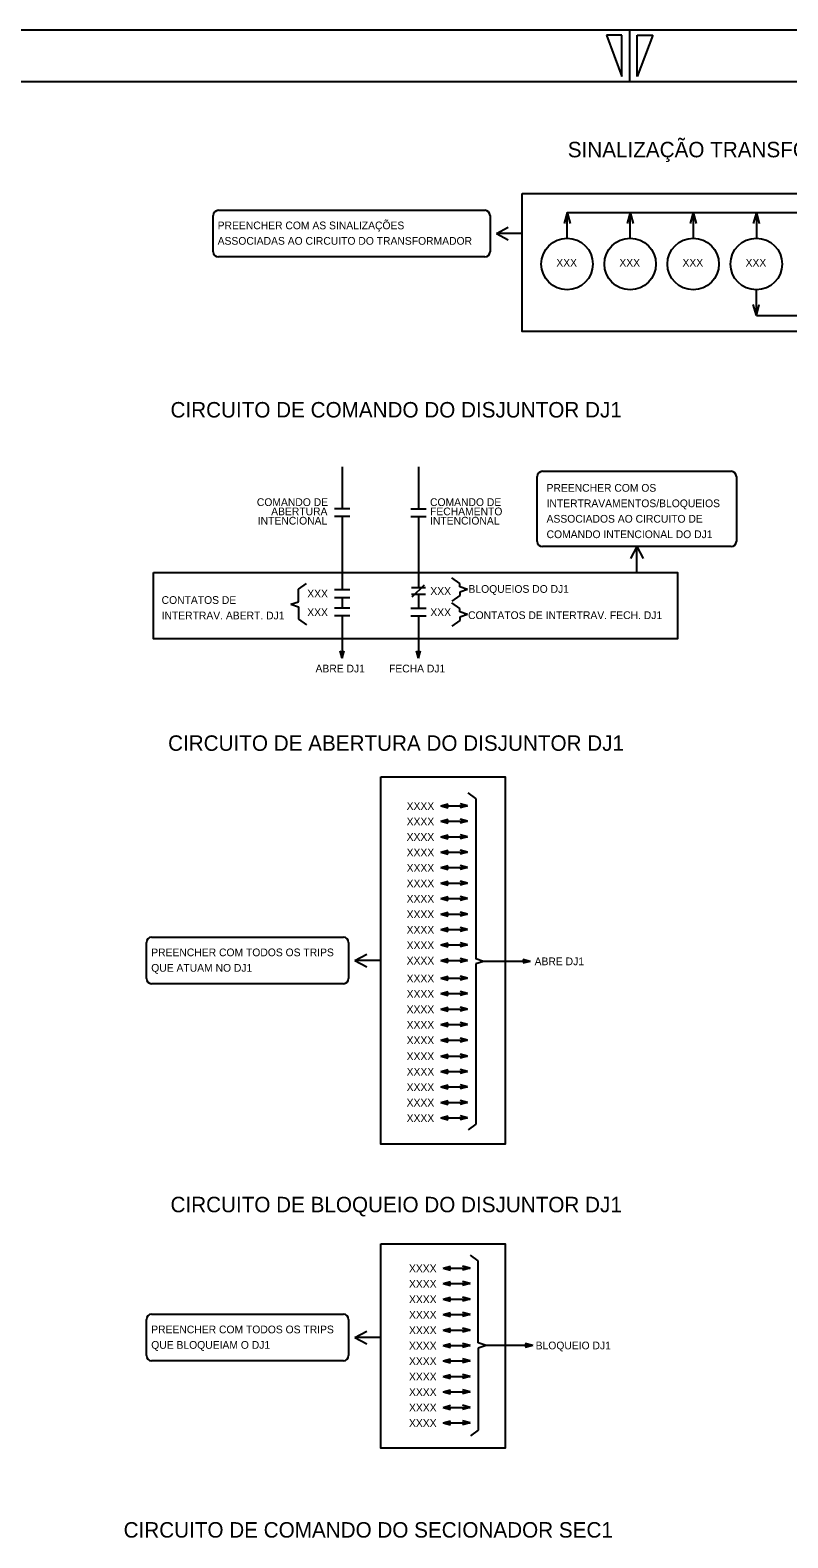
# Model space of a CAD drawing. Extents: x 563 to 1404, y 358 to 952.
# Drawn here: x 1102.2 to 1249.3, y 659.5 to 952 of the extents above; entities that cross this region are included whole.
import ezdxf

# ---------------------------------------------------------------- set-up
doc = ezdxf.new("R2010")
doc.units = 0
doc.layers.add('New Level (0)', color=7, linetype='Continuous')

# ---------------------------------------------------------------- blocks, each defined once
blk = doc.blocks.new('39')
for p, q in [((0, 0), (1.45, 0.39)), ((0, 0), (5.22, 0)), ((0, 0), (1.45, -0.39)), ((5.22, 0), (3.77, 0.39)), ((5.22, 0), (3.77, -0.39))]:
    blk.add_line(p, q)

msp = doc.modelspace()

# ---------------------------------------------------------------- linework, layer by layer
for p, q in [((1206.46, 916.59), (1205.87, 914.42)), ((1206.46, 911.59), (1206.46, 916.59)), ((1206.46, 916.59), (1265.58, 916.59)), ((1206.46, 916.59), (1207.04, 914.42)), ((1218.7, 916.59), (1218.12, 914.42)), ((1218.7, 911.59), (1218.7, 916.59)), ((1218.7, 916.59), (1219.28, 914.42)), ((1230.94, 916.59), (1230.36, 914.42)), ((1230.94, 916.59), (1230.94, 911.59)), ((1230.94, 916.59), (1231.53, 914.42)), ((1243.19, 916.59), (1242.6, 914.42)), ((1243.19, 916.59), (1243.19, 911.59)), ((1243.19, 916.59), (1243.77, 914.42)), ((1243.19, 896.59), (1243.19, 901.59)), ((1243.19, 896.59), (1242.6, 898.77)), ((1243.19, 896.59), (1243.77, 898.77)), ((1243.19, 896.59), (1265.58, 896.59)), ((1162.82, 867.28), (1162.82, 859.1)), ((1177.61, 867.28), (1177.61, 859.1)), ((1164.32, 859.1), (1161.32, 859.1)), ((1164.32, 857.6), (1161.32, 857.6)), ((1162.82, 857.6), (1162.82, 843.36)), ((1176.11, 859.1), (1179.11, 859.1)), ((1176.11, 857.6), (1179.11, 857.6)), ((1177.61, 857.6), (1177.61, 843.86)), ((1185.62, 844.64), (1184.12, 845.72)), ((1154.36, 843.55), (1155.86, 844.63)), ((1154.36, 841.08), (1154.36, 843.55)), ((1164.32, 843.36), (1161.32, 843.36)), ((1176.26, 843.86), (1178.96, 843.86)), ((1178.96, 842.51), (1176.26, 842.51)), ((1176.42, 842), (1178.8, 844.38)), ((1177.61, 842.36), (1177.61, 839.86)), ((1185.62, 843.96), (1185.62, 844.64)), ((1187.12, 843.46), (1185.62, 843.96)), ((1187.12, 843.46), (1185.62, 842.96)), ((1185.62, 842.96), (1185.62, 842.27)), ((1152.86, 840.58), (1154.36, 841.08)), ((1152.86, 840.58), (1154.36, 840.08)), ((1154.36, 840.08), (1154.36, 837.68)), ((1164.32, 841.86), (1161.32, 841.86)), ((1164.32, 839.86), (1161.32, 839.86)), ((1162.82, 841.86), (1162.82, 839.86)), ((1176.11, 839.86), (1179.11, 839.86)), ((1176.11, 839.86), (1179.11, 839.86)), ((1185.62, 842.27), (1184.12, 841.19)), ((1185.62, 839.78), (1184.12, 840.87)), ((1185.62, 839.1), (1185.62, 839.78)), ((1154.36, 837.68), (1155.86, 836.6)), ((1164.32, 838.36), (1161.32, 838.36)), ((1162.82, 838.36), (1162.82, 830.12)), ((1176.11, 838.36), (1179.11, 838.36)), ((1176.11, 838.36), (1179.11, 838.36)), ((1177.61, 838.36), (1177.61, 830.12)), ((1185.62, 837.42), (1184.12, 836.33)), ((1187.12, 838.6), (1185.62, 839.1)), ((1187.12, 838.6), (1185.62, 838.1)), ((1185.62, 838.1), (1185.62, 837.42)), ((1162.82, 830.12), (1162.43, 831.57)), ((1162.82, 830.12), (1163.21, 831.57)), ((1177.61, 830.12), (1177.22, 831.57)), ((1177.61, 830.12), (1178, 831.57)), ((1181.94, 801.5), (1183.39, 801.89)), ((1181.94, 801.5), (1187.16, 801.5)), ((1181.94, 801.5), (1183.39, 801.11)), ((1187.16, 801.5), (1185.71, 801.89)), ((1187.16, 801.5), (1185.71, 801.11)), ((1188.76, 802.92), (1187.26, 804)), ((1188.76, 802.92), (1188.76, 771.82)), ((1181.94, 798.5), (1183.39, 798.89)), ((1181.94, 798.5), (1187.16, 798.5)), ((1181.94, 798.5), (1183.39, 798.11)), ((1187.16, 798.5), (1185.71, 798.89)), ((1187.16, 798.5), (1185.71, 798.11)), ((1181.94, 795.5), (1183.39, 795.89)), ((1181.94, 795.5), (1187.16, 795.5)), ((1181.94, 795.5), (1183.39, 795.11)), ((1187.16, 795.5), (1185.71, 795.89)), ((1187.16, 795.5), (1185.71, 795.11)), ((1190.26, 771.32), (1188.76, 771.82)), ((1190.26, 771.32), (1188.76, 770.82)), ((1188.76, 770.82), (1188.76, 739.73)), ((1199.32, 771.32), (1190.26, 771.32)), ((1199.32, 771.32), (1197.87, 771.71)), ((1199.32, 771.32), (1197.87, 770.94)), ((1181.94, 768.06), (1183.39, 768.44)), ((1181.94, 768.06), (1187.16, 768.06)), ((1181.94, 768.06), (1183.39, 767.67)), ((1187.16, 768.06), (1185.71, 768.44)), ((1187.16, 768.06), (1185.71, 767.67)), ((1181.94, 752.96), (1183.39, 753.35)), ((1181.94, 752.96), (1187.16, 752.96)), ((1181.94, 752.96), (1183.39, 752.57)), ((1187.16, 752.96), (1185.71, 753.35)), ((1187.16, 752.96), (1185.71, 752.57)), ((1188.76, 739.73), (1187.26, 738.65)), ((1189.23, 713.23), (1187.73, 714.31)), ((1182.41, 711.81), (1183.86, 712.2)), ((1182.41, 711.81), (1187.63, 711.81)), ((1182.41, 711.81), (1183.86, 711.43)), ((1187.63, 711.81), (1186.18, 712.2)), ((1187.63, 711.81), (1186.18, 711.43)), ((1189.23, 697.31), (1189.23, 713.23)), ((1182.41, 705.81), (1183.86, 706.2)), ((1182.41, 705.81), (1187.63, 705.81)), ((1182.41, 705.81), (1183.86, 705.43)), ((1187.63, 705.81), (1186.18, 706.2)), ((1187.63, 705.81), (1186.18, 705.43)), ((1190.73, 696.81), (1189.23, 697.31)), ((1190.73, 696.81), (1189.23, 696.31)), ((1189.23, 696.31), (1189.23, 680.4)), ((1199.79, 696.81), (1190.73, 696.81)), ((1199.79, 696.81), (1198.34, 697.2)), ((1199.79, 696.81), (1198.34, 696.43)), ((1189.23, 680.4), (1187.73, 679.31))]:
    msp.add_line(p, q)
for centre in [(1206.46, 906.59), (1218.7, 906.59), (1230.94, 906.59), (1243.19, 906.59)]:
    msp.add_circle(centre, 5)
at = {"layer": 'New Level (0)'}
for p, q in [((1403.58, 951.96), (562.58, 951.96)), ((1403.58, 951.96), (562.58, 951.96)), ((1217.08, 950.96), (1214.08, 950.96)), ((1214.08, 950.96), (1217.08, 942.96)), ((1217.08, 942.96), (1217.08, 950.96)), ((1218.58, 951.96), (1218.58, 941.96)), ((1220.08, 942.96), (1220.08, 950.96)), ((1220.08, 950.96), (1223.08, 950.96)), ((1223.08, 950.96), (1220.08, 942.96)), ((1393.58, 941.96), (572.58, 941.96)), ((1137.78, 908.98), (1137.78, 916.01)), ((1138.78, 917.01), (1160.63, 917.01)), ((1160.63, 917.01), (1190.51, 917.01)), ((1191.51, 916.01), (1191.51, 908.98)), ((1192.74, 912.5), (1195.04, 913.71)), ((1197.77, 912.5), (1192.74, 912.5)), ((1192.74, 912.5), (1195.04, 911.29)), ((1190.51, 907.98), (1138.78, 907.98)), ((1201.66, 866.38), (1238.32, 866.38)), ((1200.66, 852.79), (1200.66, 865.38)), ((1239.32, 865.38), (1239.32, 852.79)), ((1238.32, 851.79), (1201.66, 851.79)), ((1219.99, 851.79), (1218.78, 849.49)), ((1219.99, 846.76), (1219.99, 851.79)), ((1219.99, 851.79), (1221.2, 849.49)), ((1125.82, 776.01), (1133.17, 776.01)), ((1133.17, 776.01), (1163.05, 776.01)), ((1124.82, 767.98), (1124.82, 775.01)), ((1164.05, 775.01), (1164.05, 767.98)), ((1165.29, 771.5), (1167.58, 772.71)), ((1170.32, 771.5), (1165.29, 771.5)), ((1165.29, 771.5), (1167.58, 770.29)), ((1163.05, 766.98), (1125.82, 766.98)), ((1125.82, 702.87), (1133.17, 702.87)), ((1133.17, 702.87), (1163.05, 702.87)), ((1124.82, 694.84), (1124.82, 701.87)), ((1164.05, 701.87), (1164.05, 694.84)), ((1165.29, 698.36), (1167.58, 699.57)), ((1170.32, 698.36), (1165.29, 698.36)), ((1165.29, 698.36), (1167.58, 697.15)), ((1163.05, 693.84), (1125.82, 693.84))]:
    msp.add_line(p, q, dxfattribs=at)
for points in [[(1197.77, 920.29), (1261.69, 920.29), (1261.69, 893.47), (1197.77, 893.47)], [(1126.19, 846.76), (1227.89, 846.76), (1227.89, 833.87), (1126.19, 833.87)], [(1170.32, 807.12), (1194.45, 807.12), (1194.45, 735.87), (1170.32, 735.87)], [(1170.32, 716.5), (1194.45, 716.5), (1194.45, 676.86), (1170.32, 676.86)]]:
    msp.add_lwpolyline(points, close=True, dxfattribs=at)
for centre, start, end in [((1138.78, 916.01), 90, 180), ((1190.51, 916.01), 0, 90), ((1138.78, 908.98), 180, 270), ((1190.51, 908.98), 270, 0), ((1201.66, 865.38), 90, 180), ((1238.32, 865.38), 0, 90), ((1201.66, 852.79), 180, 270), ((1238.32, 852.79), 270, 0), ((1125.82, 775.01), 90, 180), ((1163.05, 775.01), 0, 90), ((1125.82, 767.98), 180, 270), ((1163.05, 767.98), 270, 0), ((1125.82, 701.87), 90, 180), ((1163.05, 701.87), 0, 90), ((1125.82, 694.84), 180, 270), ((1163.05, 694.84), 270, 0)]:
    msp.add_arc(centre, 1, start, end, dxfattribs=at)

# ---------------------------------------------------------------- block references
for p in [(1181.94, 792.5), (1181.94, 789.5), (1181.94, 786.5), (1181.94, 783.5), (1181.94, 780.5), (1181.94, 777.5), (1181.94, 774.5), (1181.94, 771.5), (1181.94, 765.06), (1181.94, 762.06), (1181.94, 759.06), (1181.94, 756.06), (1181.94, 749.96), (1181.94, 746.96), (1181.94, 743.96), (1181.94, 740.96), (1182.41, 708.81), (1182.41, 702.81), (1182.41, 699.81), (1182.41, 696.81), (1182.41, 693.81), (1182.41, 690.81), (1182.41, 687.81), (1182.41, 684.81), (1182.41, 681.81)]:
    msp.add_blockref('39', p)

# ---------------------------------------------------------------- texts
for s, height, p in [('SINALIZAÇÃO TRANSFORMADOR T1', 3, (1206.59, 927.29)), ('PREENCHER COM AS SINALIZAÇÕES', 1.5, (1138.64, 913.33)), ('ASSOCIADAS AO CIRCUITO DO TRANSFORMADOR', 1.5, (1138.64, 910.33)), ('XXX', 1.5, (1204.37, 906.09)), ('XXX', 1.5, (1216.61, 906.09)), ('XXX', 1.5, (1228.86, 906.09)), ('XXX', 1.5, (1241.1, 906.09)), ('CIRCUITO DE COMANDO DO DISJUNTOR DJ1', 3, (1129.49, 876.82)), ('PREENCHER COM OS ', 1.5, (1202.48, 862.42)), ('COMANDO DE', 1.5, (1146.25, 859.65)), ('COMANDO DE ', 1.5, (1179.86, 859.65)), ('INTERTRAVAMENTOS/BLOQUEIOS', 1.5, (1202.48, 859.42)), (' INTENCIONAL', 1.5, (1145.87, 856.05)), (' ABERTURA', 1.5, (1148.47, 857.85)), ('FECHAMENTO ', 1.5, (1179.86, 857.85)), ('INTENCIONAL', 1.5, (1179.86, 856.05)), ('ASSOCIADOS AO CIRCUITO DE ', 1.5, (1202.48, 856.42)), ('COMANDO INTENCIONAL DO DJ1', 1.5, (1202.48, 853.42)), ('XXX', 1.5, (1156.03, 841.92)), ('XXX', 1.5, (1179.92, 842.41)), ('BLOQUEIOS DO DJ1', 1.5, (1187.32, 842.81)), ('CONTATOS DE ', 1.5, (1127.76, 840.66)), ('XXX', 1.5, (1156.03, 838.29)), ('XXX', 1.5, (1179.92, 838.29)), ('INTERTRAV. ABERT. DJ1', 1.5, (1127.76, 837.66)), ('CONTATOS DE INTERTRAV. FECH. DJ1', 1.5, (1187.25, 837.72)), ('ABRE DJ1', 1.5, (1157.64, 827.37)), ('FECHA DJ1', 1.5, (1171.9, 827.37)), ('CIRCUITO DE ABERTURA DO DISJUNTOR DJ1', 3, (1129.02, 812.16)), ('XXXX', 1.5, (1175.32, 800.7)), ('XXXX', 1.5, (1175.32, 797.7)), ('XXXX', 1.5, (1175.32, 794.7)), ('XXXX', 1.5, (1175.32, 791.7)), ('XXXX', 1.5, (1175.32, 788.7)), ('XXXX', 1.5, (1175.32, 785.7)), ('XXXX', 1.5, (1175.32, 782.7)), ('XXXX', 1.5, (1175.32, 779.7)), ('XXXX', 1.5, (1175.32, 776.7)), ('XXXX', 1.5, (1175.32, 773.7)), ('PREENCHER COM TODOS OS TRIPS', 1.5, (1125.75, 772.31)), ('XXXX', 1.5, (1175.32, 770.7)), ('QUE ATUAM NO DJ1', 1.5, (1125.75, 769.31)), ('ABRE DJ1', 1.5, (1200.16, 770.57)), ('XXXX', 1.5, (1175.32, 767.26)), ('XXXX', 1.5, (1175.32, 764.26)), ('XXXX', 1.5, (1175.32, 761.26)), ('XXXX', 1.5, (1175.32, 758.26)), ('XXXX', 1.5, (1175.32, 755.26)), ('XXXX', 1.5, (1175.32, 752.16)), ('XXXX', 1.5, (1175.32, 749.16)), ('XXXX', 1.5, (1175.32, 746.16)), ('XXXX', 1.5, (1175.32, 743.16)), ('XXXX', 1.5, (1175.32, 740.16)), ('CIRCUITO DE BLOQUEIO DO DISJUNTOR DJ1', 3, (1129.49, 722.65)), ('XXXX', 1.5, (1175.78, 711.02)), ('XXXX', 1.5, (1175.78, 708.02)), ('XXXX', 1.5, (1175.78, 705.02)), ('XXXX', 1.5, (1175.78, 702.02)), ('PREENCHER COM TODOS OS TRIPS', 1.5, (1125.75, 699.17)), ('XXXX', 1.5, (1175.78, 699.02)), ('QUE BLOQUEIAM O DJ1', 1.5, (1125.75, 696.17)), ('XXXX', 1.5, (1175.78, 696.02)), ('BLOQUEIO DJ1', 1.5, (1200.36, 696.06)), ('XXXX', 1.5, (1175.78, 693.02)), ('XXXX', 1.5, (1175.78, 690.02)), ('XXXX', 1.5, (1175.78, 687.02)), ('XXXX', 1.5, (1175.78, 684.02)), ('XXXX', 1.5, (1175.78, 681.02)), ('CIRCUITO DE COMANDO DO SECIONADOR SEC1', 3, (1120.39, 659.54))]:
    msp.add_text(s, height=height).set_placement(p)

doc.saveas('drawing.dxf')
